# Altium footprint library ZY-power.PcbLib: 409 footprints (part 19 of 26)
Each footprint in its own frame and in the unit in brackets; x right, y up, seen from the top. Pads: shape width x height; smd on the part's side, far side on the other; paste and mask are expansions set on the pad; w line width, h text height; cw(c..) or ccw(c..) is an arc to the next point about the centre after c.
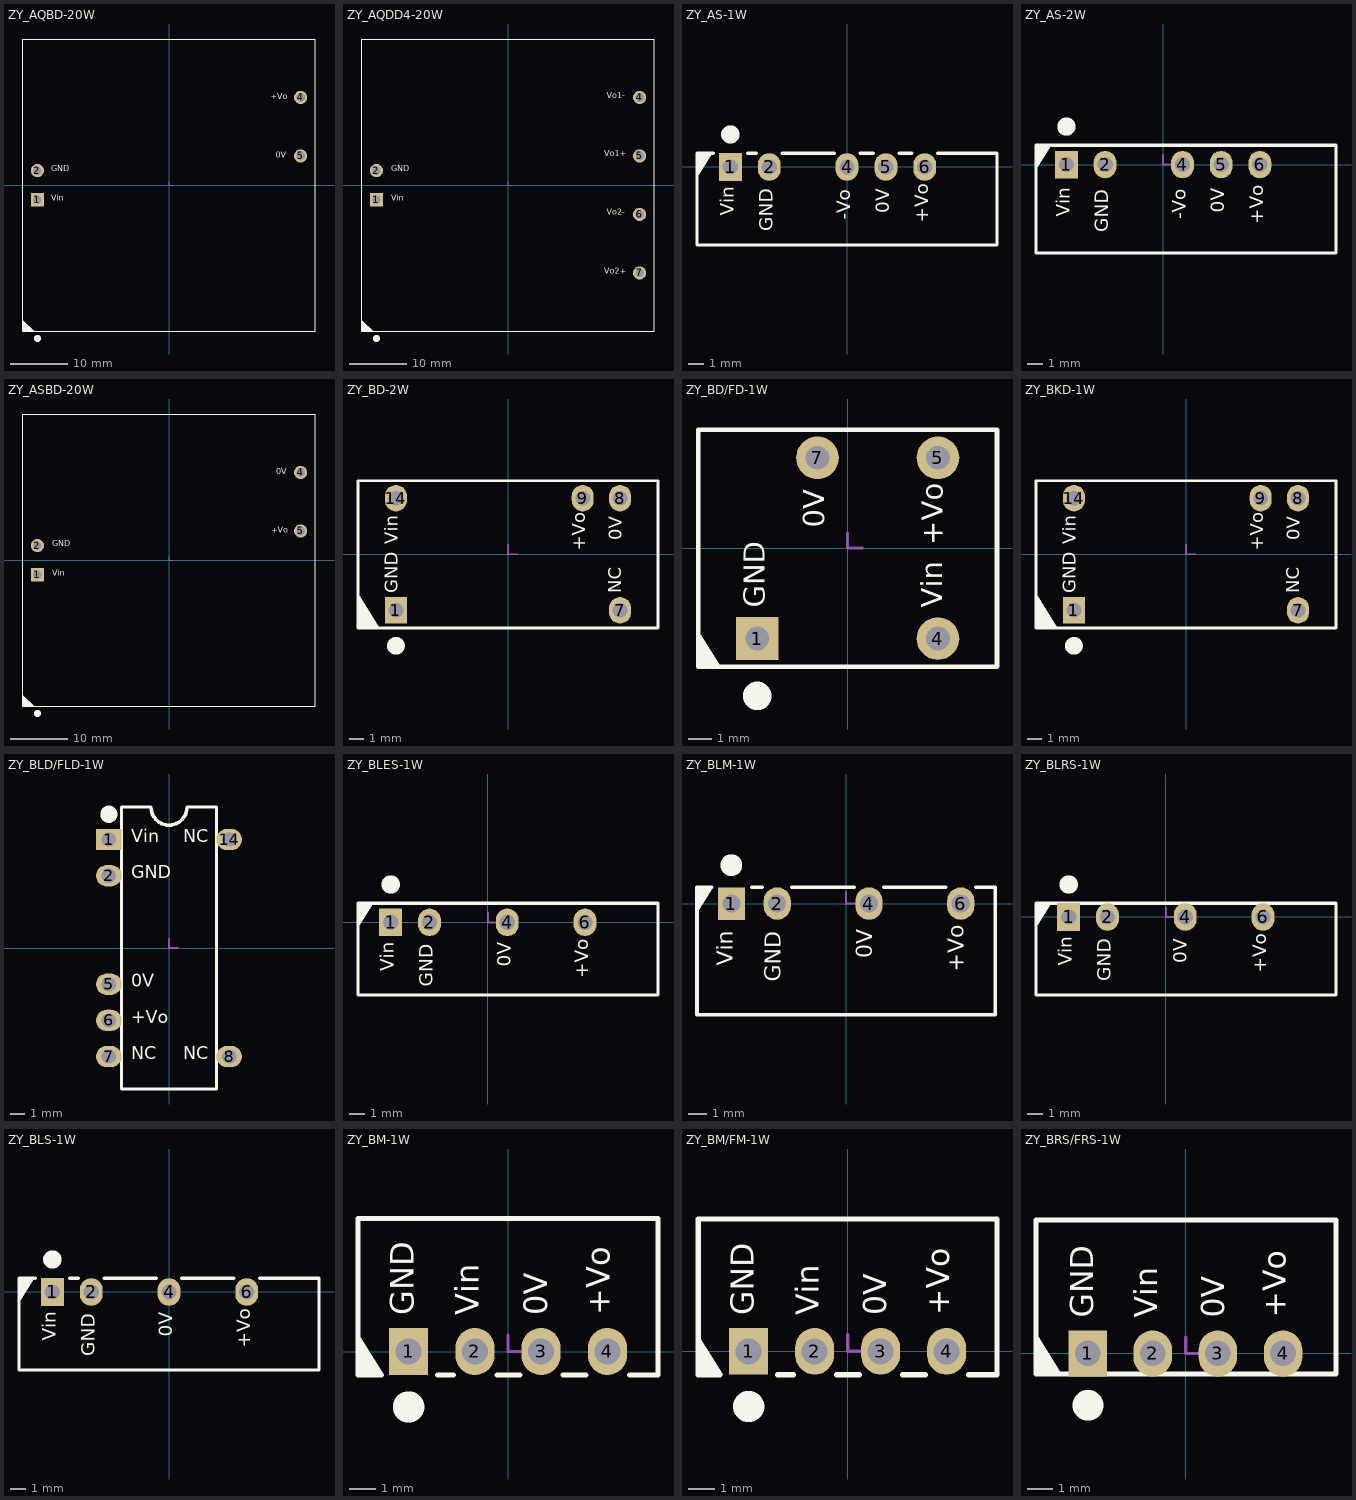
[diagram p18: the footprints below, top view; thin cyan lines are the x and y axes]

## ZY_AQBD-20W [mm]
height 12.8
pads (4):
  rect 2.3x2.3 hole 1.5: 1(-22.86,-2.54)
  round 2.3 hole 1.5: 2(-22.86,2.54) 4(22.86,15.24) 5(22.86,5.08)
Top Overlay:
  circle w1: c-22.86,-26.625 r0.1
  region: -25.4,-25.4 -23.425,-25.4 -25.4,-23.425
  lines w0.2: -25.4,-25.4 25.4,-25.4 25.4,25.4 -25.4,25.4 -25.4,-25.4
  text "0V" at 18.517,4.447 h1.78
  text "+Vo" at 17.653,14.607 h1.78
  text "Vin" at -20.447,-3.046 h1.78
  text "GND" at -20.447,2.034 h1.78
Mechanical 15:
  lines w0.127: 0,0.635 0,0 0.635,0

## ZY_AQDD4-20W [mm]
pads (6):
  rect 2.3x2.3 hole 1.5: 1(-22.86,-2.54)
  round 2.3 hole 1.5: 2(-22.86,2.54) 4(22.86,15.24) 5(22.86,5.08) 6(22.86,-5.08) 7(22.86,-15.24)
Top Overlay:
  circle w1: c-22.86,-26.625 r0.1
  region: -25.4,-25.4 -23.425,-25.4 -25.4,-23.425
  lines w0.2: -25.4,-25.4 25.4,-25.4 25.4,25.4 -25.4,25.4 -25.4,-25.4
  text "Vo1-" at 17.125,14.732 h1.78
  text "Vo2-" at 17.125,-5.461 h1.78
  text "Vo2+" at 16.764,-15.748 h1.78
  text "Vo1+" at 16.764,4.699 h1.78
  text "Vin" at -20.32,-3.046 h1.78
  text "GND" at -20.32,2.034 h1.78
Mechanical 15:
  lines w0.127: 0,0.635 0,0 0.635,0

## ZY_AS-1W [mm] "定压输入隔离非稳压正、负双输出"
height 10.1
pads (5):
  rect 1.5x1.8 hole 1: 1(-7.62,0)
  oval 1.5x1.8 hole 1: 2(-5.08,0) 4(0,0) 5(2.54,0) 6(5.08,0)
Top Overlay:
  circle w1: c-7.62,2.125 r0.1
  region: -9.8,-0.686 -9.8,0.9 -8.806,0.9
  lines w0.2: -8.72,0.9 -9.8,0.9 -9.8,-5.1 9.8,-5.1 9.8,0.9 5.9,0.9 ; -6.5,0.9 -5.9,0.9 ; -4.26,0.9 -0.82,0.9 ; 0.846,0.9 1.72,0.9 ; 3.386,0.9 4.26,0.9
  text "-Vo" at 0.508,-3.462 h1.52
  text "0V" at 3.048,-3.034 h1.52
  text "Vin" at -7.112,-3.181 h1.52
  text "GND" at -4.572,-4.191 h1.52
  text "+Vo" at 5.588,-3.649 h1.52
Mechanical 15:
  lines w0.127: 0,0.635 0,0 0.635,0
3D body "zhenjao01.stp": height 8.36, standoff -4.08, extent 1.84,-1.48 3.24,0.12
3D body "zhenjao01.stp": height 8.36, standoff -4.08, extent -8.32,-1.48 -6.92,0.12
3D body "zhenjao01.stp": height 8.36, standoff -4.08, extent -5.78,-1.48 -4.38,0.12
3D body "zhenjao01.stp": height 8.36, standoff -4.08, extent -0.7,-1.48 0.7,0.12
3D body "zhenjao01.stp": height 8.36, standoff -4.08, extent 4.38,-1.48 5.78,0.12
3D body: height 10.1, standoff 0, extent -9.8,-5.1 9.8,0.9

## ZY_AS-2W [mm] "定压输入隔离非稳压正、负双输出"
height 10
pads (5):
  rect 1.5x1.8 hole 1: 1(-6.35,0)
  oval 1.5x1.8 hole 1: 2(-3.81,0) 4(1.27,0) 5(3.81,0) 6(6.35,0)
Top Overlay:
  circle w1: c-6.35,2.495 r0.1
  region: -8.35,-0.316 -8.35,1.27 -7.356,1.27
  lines w0.2: 11.35,1.25 11.35,-5.8 -8.35,-5.8 -8.35,1.27 11.35,1.27
  text "+Vo" at 6.858,-3.903 h1.52
  text "0V" at 4.318,-3.163 h1.52
  text "GND" at -3.302,-4.445 h1.52
  text "Vin" at -5.842,-3.435 h1.52
  text "-Vo" at 1.778,-3.591 h1.52
Mechanical 15:
  lines w0.127: 0,0.635 0,0 0.635,0

## ZY_ASBD-20W [mm]
height 12.8
pads (4):
  rect 2.3x2.3 hole 1.5: 1(-22.86,-2.54)
  round 2.3 hole 1.5: 2(-22.86,2.54) 4(22.86,15.24) 5(22.86,5.08)
Top Overlay:
  circle w1: c-22.86,-26.625 r0.1
  region: -25.4,-25.4 -23.425,-25.4 -25.4,-23.425
  lines w0.2: -25.4,-25.4 -25.4,25.4 25.4,25.4 25.4,-25.4 -25.4,-25.4
  text "GND" at -20.32,2.034 h1.78
  text "Vin" at -20.32,-3.046 h1.78
  text "0V" at 18.644,14.607 h1.78
  text "+Vo" at 17.78,4.447 h1.78
Mechanical 15:
  lines w0.127: 0,0.635 0,0 0.635,0

## ZY_BD-2W [mm]
height 8.1
pads (5):
  rect 1.5x1.8 hole 1: 1(-7.62,-3.81)
  oval 1.5x1.8 hole 1: 7(7.62,-3.81) 8(7.62,3.81) 9(5.08,3.81) 14(-7.62,3.81)
Top Overlay:
  circle w1: c-7.62,-6.225 r0.1
  region: -10.2,-2.67 -10.2,-5 -8.74,-5
  lines w0.2: -10.2,-5 10.2,-5 10.2,5 -10.2,5 -10.2,-5
  text "GND" at -7.188,-2.667 h1.52
  text "NC" at 8.001,-2.667 h1.52
  text "Vin" at -7.188,0.695 h1.52
  text "+Vo" at 5.563,0.227 h1.52
  text "0V" at 8.052,0.967 h1.52
Mechanical 15:
  lines w0.127: 0,0.635 0,0 0.635,0

## ZY_BD/FD-1W [mm] "定压输入隔离非稳压单输出"
height 7.7
pads (4):
  rect 1.8x1.8 hole 1: 1(-3.81,-3.81)
  round 1.8 hole 1: 4(3.81,-3.81) 5(3.81,3.81) 7(-1.27,3.81)
Top Overlay:
  circle w1: c-3.81,-6.229 r0.1
  region: -6.35,-3.418 -6.35,-5.004 -5.356,-5.004
  lines w0.2: -6.299,-5.004 -6.299,4.996 6.301,4.996 6.301,-5.004 -6.299,-5.004
  text "GND" at -3.2,-2.516 h1.52
  text "Vin" at 4.293,-2.515 h1.52
  text "+Vo" at 4.318,0.124 h1.52
  text "0V" at -0.686,0.864 h1.52
Mechanical 15:
  lines w0.127: 0,0.635 0,0 0.635,0

## ZY_BKD-1W [mm]
height 8.1
pads (5):
  rect 1.5x1.8 hole 1: 1(-7.62,-3.81)
  oval 1.5x1.8 hole 1: 7(7.62,-3.81) 8(7.62,3.81) 9(5.08,3.81) 14(-7.62,3.81)
Top Overlay:
  circle w1: c-7.62,-6.225 r0.1
  region: -10.2,-2.67 -10.2,-5 -8.74,-5
  lines w0.2: -10.2,-5 -10.2,5 10.2,5 10.2,-5 -10.2,-5
  text "0V" at 8.052,0.967 h1.52
  text "+Vo" at 5.563,0.227 h1.52
  text "Vin" at -7.188,0.695 h1.52
  text "NC" at 8.001,-2.667 h1.52
  text "GND" at -7.188,-2.667 h1.52
Mechanical 15:
  lines w0.127: 0,0.635 0,0 0.635,0

## ZY_BLD/FLD-1W [mm] "定压输入隔离非稳压单输出"
height 5.5
pads (7):
  rect 1.8x1.5 hole 1: 1(-4.225,7.62)
  oval 1.8x1.5 hole 1: 2(-4.225,5.08) 5(-4.225,-2.54) 6(-4.225,-5.08) 7(-4.225,-7.62) 8(4.225,-7.62) 14(4.225,7.62)
Top Overlay:
  circle w1: c-4.225,9.398 r0.1
  lines w0.2: -1.27,9.9 -3.336,9.9 -3.336,-9.9 3.344,-9.9 3.344,9.9 1.27,9.9
  lines w0.254: -1.27,9.9 ccw(c0,9.9) 0,8.63 ccw(c0,9.9) 1.27,9.9
  text "NC" at 1.016,7.112 h1.52
  text "NC" at 1.016,-8.128 h1.52
  text "NC" at -2.668,-8.128 h1.52
  text "0V" at -2.668,-3.048 h1.52
  text "+Vo" at -2.668,-5.588 h1.52
  text "GND" at -2.668,4.572 h1.52
  text "Vin" at -2.667,7.112 h1.52
Mechanical 15:
  lines w0.127: 0,0.635 0,0 0.635,0

## ZY_BLES-1W [mm]
height 10
pads (4):
  rect 1.5x1.8 hole 1: 1(-6.35,0)
  oval 1.5x1.8 hole 1: 2(-3.81,0) 4(1.27,0) 6(6.35,0)
Top Overlay:
  circle w1: c-6.35,2.475 r0.1
  region: -8.48,-0.336 -8.48,1.25 -7.486,1.25
  lines w0.2: -8.48,-4.75 -8.48,1.25 11.12,1.25 11.12,-4.75 -8.48,-4.75
  text "+Vo" at 6.858,-3.649 h1.52
  text "0V" at 1.803,-2.909 h1.52
  text "GND" at -3.302,-4.191 h1.52
  text "Vin" at -5.842,-3.181 h1.52
Mechanical 15:
  lines w0.127: 0,0.635 0,0 0.635,0

## ZY_BLM-1W [mm]
height 7.5
pads (4):
  rect 1.5x1.8 hole 1: 1(-6.35,0)
  oval 1.5x1.8 hole 1: 2(-3.81,0) 4(1.27,0) 6(6.35,0)
Top Overlay:
  circle w1: c-6.35,2.125 r0.1
  region: -8.25,-0.544 -8.25,0.864 -7.368,0.864
  lines w0.2: -7.45,0.9 -8.25,0.9 -8.25,-6.15 8.25,-6.15 8.25,0.9 7.17,0.9 ; -5.23,0.9 -4.63,0.9 ; -2.99,0.9 0.45,0.9 ; 2.09,0.9 5.53,0.9
  text "+Vo" at 6.833,-3.776 h1.52
  text "0V" at 1.753,-3.036 h1.52
  text "GND" at -3.302,-4.318 h1.52
  text "Vin" at -5.969,-3.435 h1.52
Mechanical 15:
  lines w0.127: 0,0.635 0,0 0.635,0

## ZY_BLRS-1W [mm]
height 10
pads (4):
  rect 1.5x1.8 hole 1: 1(-6.35,0)
  oval 1.5x1.8 hole 1: 2(-3.81,0) 4(1.27,0) 6(6.35,0)
Top Overlay:
  circle w1: c-6.35,2.125 r0.1
  region: -8.48,-0.686 -8.48,0.9 -7.486,0.9
  lines w0.2: -8.48,-5.1 11.12,-5.1 11.12,0.9 -8.48,0.9 -8.48,-5.1
  text "Vin" at -5.842,-3.181 h1.52
  text "GND" at -3.302,-4.191 h1.52
  text "0V" at 1.676,-3.036 h1.52
  text "+Vo" at 6.858,-3.649 h1.52
Mechanical 15:
  lines w0.127: 0,0.635 0,0 0.635,0

## ZY_BLS-1W [mm] "定压输入隔离非稳压单输出"
height 10.1
pads (4):
  rect 1.5x1.8 hole 1: 1(-7.62,0)
  oval 1.5x1.8 hole 1: 2(-5.08,0) 4(0,0) 6(5.08,0)
Top Overlay:
  circle w1: c-7.62,2.125 r0.1
  region: -9.8,-0.686 -9.8,0.9 -8.806,0.9
  lines w0.2: -8.72,0.9 -9.8,0.9 -9.8,-5.1 9.8,-5.1 9.8,0.9 5.9,0.9 ; -6.5,0.9 -5.9,0.9 ; -4.26,0.9 -0.82,0.9 ; 0.82,0.9 4.26,0.9
  text "Vin" at -7.112,-3.181 h1.52
  text "GND" at -4.572,-4.191 h1.52
  text "0V" at 0.508,-2.909 h1.52
  text "+Vo" at 5.588,-3.649 h1.52
Mechanical 15:
  lines w0.127: 0,0.635 0,0 0.635,0
3D body "zhenjao01.stp": height 8.36, standoff -4.08, extent -8.32,-1.48 -6.92,0.12
3D body "zhenjao01.stp": height 8.36, standoff -4.08, extent -5.78,-1.48 -4.38,0.12
3D body "zhenjao01.stp": height 8.36, standoff -4.08, extent -0.7,-1.48 0.7,0.12
3D body "zhenjao01.stp": height 8.36, standoff -4.08, extent 4.38,-1.48 5.78,0.12
3D body: height 10.1, standoff 0, extent -9.8,-5.1 9.8,0.9

## ZY_BM-1W [mm] "定压输入隔离非稳压单输出"
height 7.5
pads (4):
  rect 1.5x1.8 hole 1: 1(-3.81,0)
  oval 1.5x1.8 hole 1: 2(-1.27,0) 3(1.27,0) 4(3.81,0)
Top Overlay:
  circle w1: c-3.81,-2.125 r0.1
  region: -5.75,0.686 -5.75,-0.889 -4.763,-0.889
  lines w0.2: -4.86,-0.9 -5.75,-0.9 -5.75,5.1 5.75,5.1 5.75,-0.9 4.656,-0.9 ; -2.69,-0.9 -2.09,-0.9 ; -0.424,-0.9 0.45,-0.9 ; 2.116,-0.9 2.99,-0.9
  text "GND" at -3.302,1.396 h1.52
  text "Vin" at -0.813,1.397 h1.52
  text "0V" at 1.803,1.396 h1.52
  text "+Vo" at 4.216,1.396 h1.52
Mechanical 15:
  lines w0.127: 0,0.635 0,0 0.635,0

## ZY_BM/FM-1W [mm]
height 10
pads (4):
  rect 1.5x1.8 hole 1: 1(-3.81,0)
  oval 1.5x1.8 hole 1: 2(-1.27,0) 3(1.27,0) 4(3.81,0)
Top Overlay:
  circle w1: c-3.81,-2.125 r0.1
  region: -5.8,0.686 -5.8,-0.889 -4.813,-0.889
  lines w0.2: -4.91,-0.9 -5.75,-0.9 -5.75,5.1 5.75,5.1 5.75,-0.9 4.656,-0.9 ; -2.69,-0.9 -2.09,-0.9 ; -0.424,-0.9 0.45,-0.9 ; 2.116,-0.9 2.99,-0.9
  text "GND" at -3.302,1.396 h1.52
  text "Vin" at -0.813,1.397 h1.52
  text "0V" at 1.803,1.396 h1.52
  text "+Vo" at 4.216,1.396 h1.52
Mechanical 15:
  lines w0.127: 0,0.635 0,0 0.635,0
3D body "zhenjao01.stp": height 8.36, standoff -4.08, extent 3.11,-0.12 4.51,1.48
3D body "zhenjao01.stp": height 8.36, standoff -4.08, extent 0.57,-0.12 1.97,1.48
3D body "zhenjao01.stp": height 8.36, standoff -4.08, extent -1.97,-0.12 -0.57,1.48
3D body: height 10.1, standoff 0, extent -5.75,-0.9 5.75,5.1
3D body "zhenjao01.stp": height 8.36, standoff -4.08, extent -4.51,-0.12 -3.11,1.48

## ZY_BRS/FRS-1W [mm]
height 10
pads (4):
  rect 1.5x1.8 hole 1: 1(-3.823,0)
  oval 1.5x1.8 hole 1: 2(-1.283,0) 3(1.257,0) 4(3.797,0)
Top Overlay:
  circle w1: c-3.81,-2.025 r0.1
  region: -5.837,0.786 -5.837,-0.8 -4.844,-0.8
  lines w0.2: -5.837,-0.8 -5.837,5.2 5.863,5.2 5.863,-0.8 -5.837,-0.8
  text "+Vo" at 4.204,1.396 h1.52
  text "0V" at 1.791,1.396 h1.52
  text "Vin" at -0.826,1.397 h1.52
  text "GND" at -3.315,1.396 h1.52
Mechanical 15:
  lines w0.127: 0,0.635 0,0 0.635,0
